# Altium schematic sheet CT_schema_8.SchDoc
size 277 x 170 mm
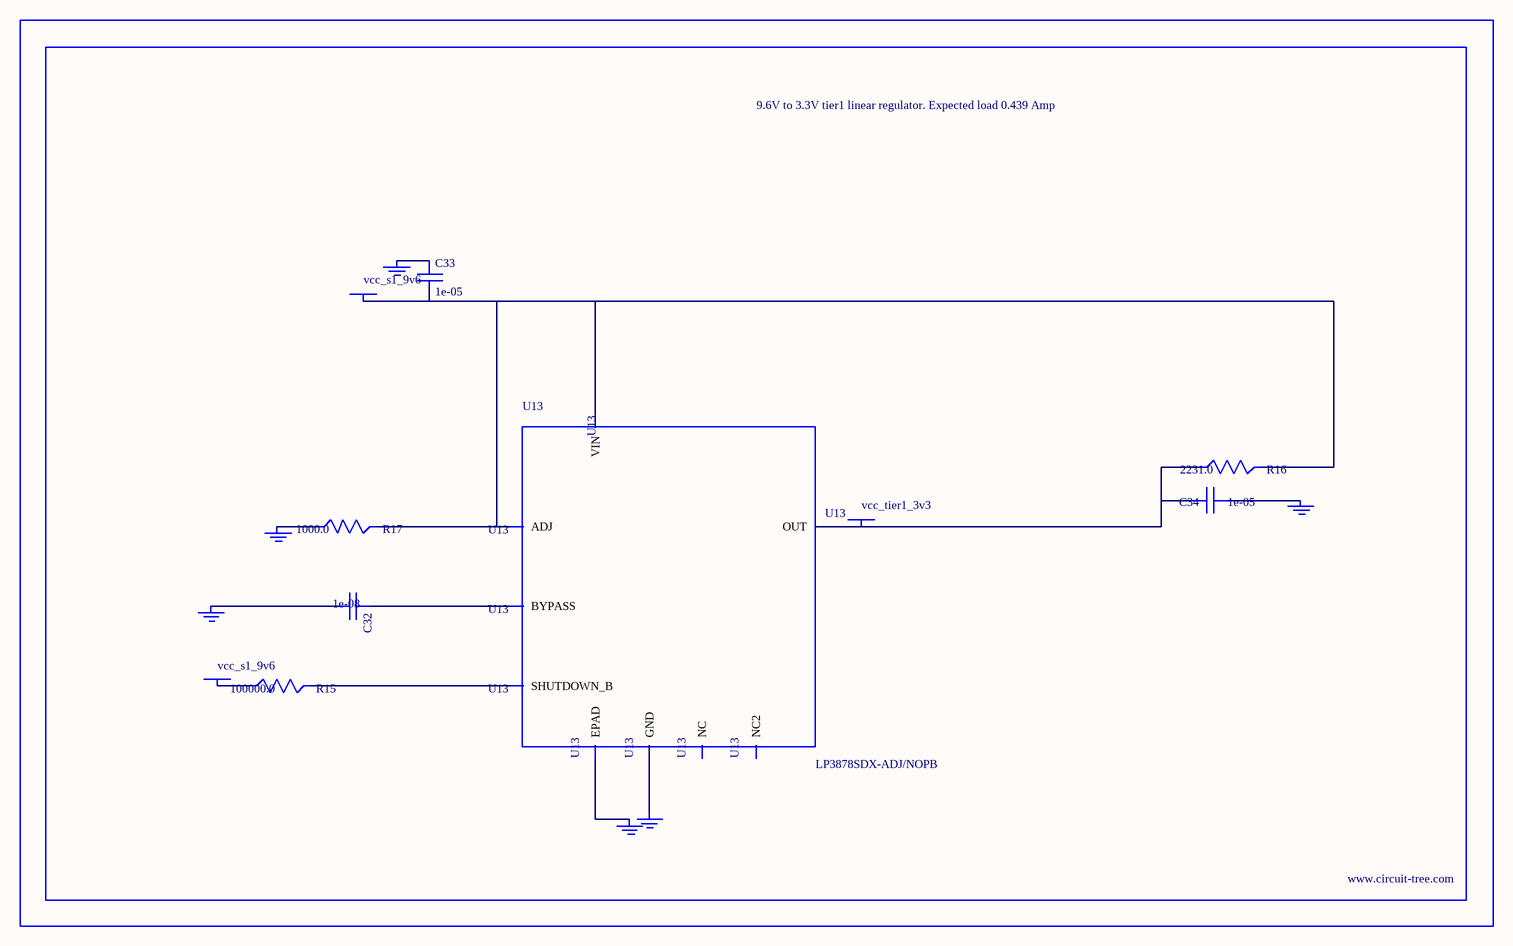
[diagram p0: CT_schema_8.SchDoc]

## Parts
BORDER7  (no value)
C32  1e-08  [C0402]
C33  1e-05  [C1206]
C34  1e-05  [C1210]
GND_INSTANCE_7_0  (no value)
GND_INSTANCE_7_1  (no value)
GND_INSTANCE_7_2  (no value)
GND_INSTANCE_7_3  (no value)
GND_INSTANCE_7_4  (no value)
GND_INSTANCE_7_5  (no value)
POWER_INSTANCE_7_0  vcc_s1_9v6
POWER_INSTANCE_7_1  vcc_s1_9v6
POWER_INSTANCE_7_2  vcc_tier1_3v3
R15  100000.0  [R0603]
R16  2231.0  [R0603]
R17  1000.0  [R0603]
U13  LP3878SDX-ADJ/NOPB  [WSON-8]

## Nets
NetC32_1: C32.1 U13.1(BYPASS)
NetC32_2: C32.2 GND_INSTANCE_7_0.0(GND)
NetC33_1: C33.1 GND_INSTANCE_7_1.0(GND)
NetC33_2: C33.2 POWER_INSTANCE_7_0.0(PWR) R16.2 R17.2 U13.4(VIN) U13.6(ADJ)
NetC34_1: C34.1 GND_INSTANCE_7_2.0(GND)
NetC34_2: C34.2 POWER_INSTANCE_7_2.0(PWR) R16.1 U13.5(OUT)
NetGND_INSTANCE_7_3_0: GND_INSTANCE_7_3.0(GND) R17.1
NetGND_INSTANCE_7_4_0: GND_INSTANCE_7_4.0(GND) U13.PAD(EPAD)
NetGND_INSTANCE_7_5_0: GND_INSTANCE_7_5.0(GND) U13.3(GND)
NetPOWER_INSTANCE_7_1_0: POWER_INSTANCE_7_1.0(PWR) R15.1
NetR15_2: R15.2 U13.8(SHUTDOWN_B)

Not connected (* = marked no-connect by the designer): U13 2(NC) 7(NC2)

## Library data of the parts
BORDER7 = BORDER_PAGE7
C32 = C0402C103K3RAC
C33 = C1206C106K3RACTU
C34 = GRM32DR61E106MA12L
GND_INSTANCE_7_0-GND_INSTANCE_7_5 = GND
POWER_INSTANCE_7_0-POWER_INSTANCE_7_2 = PWR
R15 = RC0603JR-07100KL
R16 = R16
R17 = RC0603JR-071KL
